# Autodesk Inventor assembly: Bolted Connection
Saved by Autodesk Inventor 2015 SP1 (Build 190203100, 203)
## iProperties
Created: 2011-06
Part Number: Bolted Connection
Document SubType Name: Assembly
Designer: Guilherme Augusto Franco de Souza
ClientObjectVersion: 1
Author: Guilherme Augusto Franco de Souza
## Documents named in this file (1)
- E:\Visitor Experience Project\WSI2015 - Visitor Experience Project\#46- Sheet Metal Technology\01- 3D Models\Outodoor Heater\2- Assemblies\Base\Design Accelerator\Bolted Connection1.iam
